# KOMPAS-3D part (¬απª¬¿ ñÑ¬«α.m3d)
File: created 22.07.2016 15:47:08, last saved 22.07.2016 15:58:27.
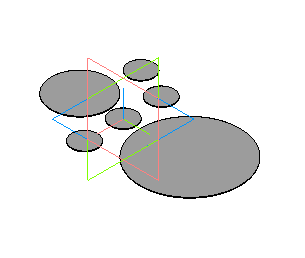
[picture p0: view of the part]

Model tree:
1. Эскиз:1
2. Операция выдавливания:1
     Толщина стенки 2 = 15; Расстояние 1 = 0.5; Расстояние 2 = 96.2519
